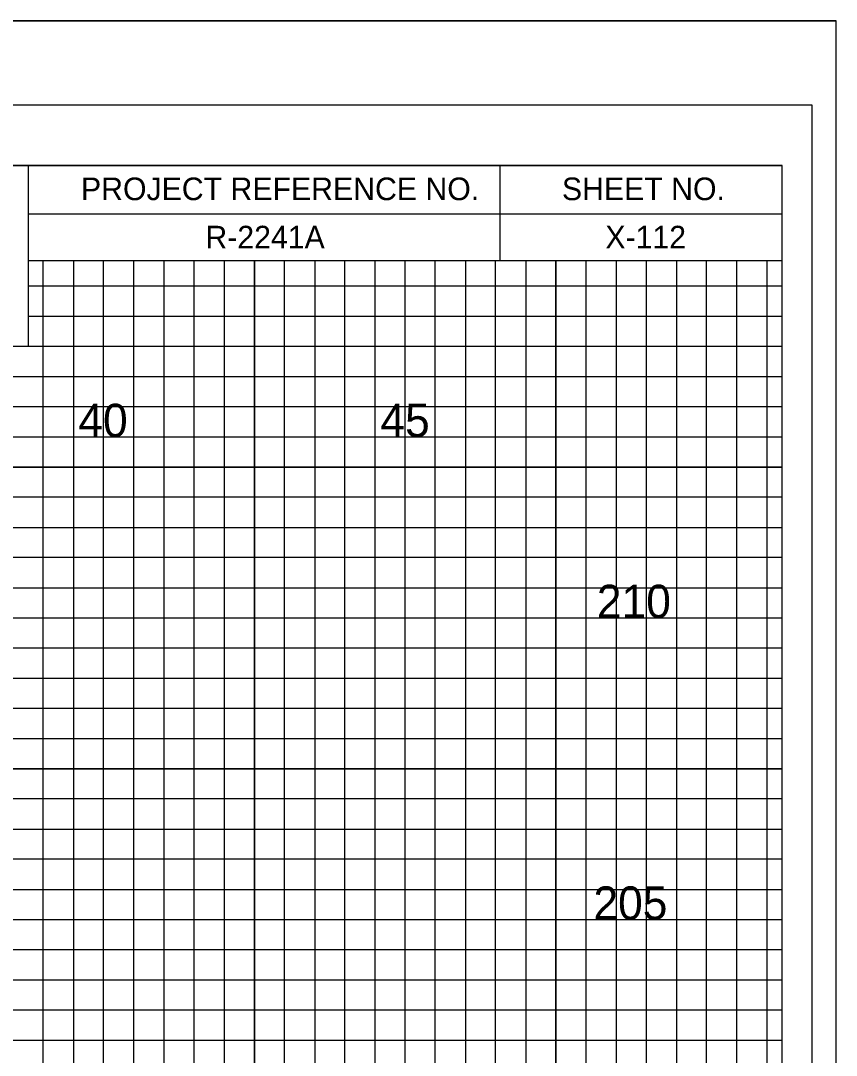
# Model space of a CAD drawing. Extents: x -4 to 103, y -2 to 492.
# Drawn here: x 89.88 to 103.4, y 121.08 to 138.23 of the extents above; entities that cross this region are included whole.
import ezdxf

# ---------------------------------------------------------------- set-up
doc = ezdxf.new("R2010")
doc.units = 0
for name, color, linetype in [('Exist XS Center Line Elevation Label', 7, 'Continuous'), ('Exist XS Ground Line', 7, 'Continuous'), ('Old_Level_10', 7, 'Continuous'), ('Old_Level_16', 7, 'Continuous'), ('Old_Level_3', 7, 'Continuous'), ('Old_Level_5', 7, 'Continuous'), ('Old_Level_8', 7, 'Continuous'), ('Prop Dimension', 7, 'Continuous'), ('Prop XS Finish Grade Earthwork', 7, 'Continuous'), ('Prop XS SE Text', 7, 'Continuous'), ('Prop XSC Text', 7, 'Continuous')]:
    doc.layers.add(name, color=color, linetype=linetype)

msp = doc.modelspace()

# ---------------------------------------------------------------- linework, layer by layer
at = {"layer": 'Old_Level_10'}
for p, q in [((91.25, 70.825), (91.25, 134.25)), ((93.75, 70.825), (93.75, 134.25)), ((96.25, 70.825), (96.25, 134.25)), ((98.75, 70.825), (98.75, 134.25)), ((101.25, 70.825), (101.25, 134.25)), ((90, 133.325), (102.5, 133.325)), ((0, 130.825), (102.5, 130.825)), ((0, 128.325), (102.5, 128.325)), ((0, 125.825), (102.5, 125.825)), ((0, 123.325), (102.5, 123.325))]:
    msp.add_line(p, q, dxfattribs=at)
at = {"layer": 'Old_Level_3'}
msp.add_line((-3.5, 138.225), (103.4, 138.225), dxfattribs=at)
at = {"layer": 'Old_Level_5'}
msp.add_lwpolyline([(103.4, 138.225), (-3.5, 138.225), (-3.5, 68.4), (103.4, 68.4)], close=True, dxfattribs=at)
at = {"layer": 'Old_Level_8'}
for points in [[(91.25, 70.825), (91.25, 134.25), (93.75, 134.25), (93.75, 70.825)], [(96.25, 70.825), (96.25, 134.25), (98.75, 134.25), (98.75, 70.825)], [(101.25, 70.825), (101.25, 134.25)], [(90, 133.325), (102.5, 133.325)], [(0, 128.325), (102.5, 128.325), (102.5, 130.825), (0, 130.825)], [(0, 123.325), (102.5, 123.325), (102.5, 125.825), (0, 125.825)]]:
    msp.add_lwpolyline(points, dxfattribs=at)
at = {"layer": 'Prop Dimension'}
for points in [[(90.25, 70.825), (90.25, 134.25), (90.75, 134.25), (90.75, 70.825)], [(91.75, 70.825), (91.75, 134.25), (92.25, 134.25), (92.25, 70.825)], [(92.75, 70.825), (92.75, 134.25), (93.25, 134.25), (93.25, 70.825)], [(94.25, 70.825), (94.25, 134.25), (94.75, 134.25), (94.75, 70.825)], [(95.25, 70.825), (95.25, 134.25), (95.75, 134.25), (95.75, 70.825)], [(96.75, 70.825), (96.75, 134.25), (97.25, 134.25), (97.25, 70.825)], [(97.75, 70.825), (97.75, 134.25), (98.25, 134.25), (98.25, 70.825)], [(99.25, 70.825), (99.25, 134.25), (99.75, 134.25), (99.75, 70.825)], [(100.25, 70.825), (100.25, 134.25)], [(100.25, 134.25), (100.75, 134.25), (100.75, 70.825), (101.75, 70.825), (101.75, 134.25), (102.25, 134.25), (102.25, 70.825)], [(102.5, 132.825), (102.5, 133.825), (90, 133.825)], [(0, 132.325), (102.5, 132.325), (102.5, 132.825), (0, 132.825)], [(0, 131.325), (102.5, 131.325), (102.5, 131.825), (0, 131.825)], [(0, 129.825), (102.5, 129.825), (102.5, 130.325), (0, 130.325)], [(0, 128.825), (102.5, 128.825), (102.5, 129.325), (0, 129.325)], [(0, 127.325), (102.5, 127.325), (102.5, 127.825), (0, 127.825)], [(0, 126.325), (102.5, 126.325), (102.5, 126.825), (0, 126.825)], [(0, 124.825), (102.5, 124.825), (102.5, 125.325), (0, 125.325)], [(0, 123.825), (102.5, 123.825), (102.5, 124.325), (0, 124.325)], [(0, 122.325), (102.5, 122.325), (102.5, 122.825), (0, 122.825)], [(0, 121.325), (102.5, 121.325), (102.5, 121.825), (0, 121.825)]]:
    msp.add_lwpolyline(points, dxfattribs=at)
at = {"layer": 'Prop XS SE Text'}
msp.add_lwpolyline([(103, 136.825), (-2.8, 136.825), (-2.8, 69.825), (103, 69.825)], close=True, dxfattribs=at)
at = {"layer": 'Prop XSC Text'}
for p, q in [((90, 135.825), (102.5, 135.825)), ((90, 135.825), (102.5, 135.825)), ((97.825, 134.25), (97.825, 135.825)), ((101.875, 135.825), (101.875, 135.825)), ((102.5, 135.825), (102.5, 135.825)), ((102.5, 134.25), (102.5, 135.825)), ((102.5, 135.825), (102.5, 135.825)), ((102.5, 135.825), (102.5, 135.825)), ((102.5, 134.25), (102.5, 135.825)), ((90, 135.025), (102.5, 135.025)), ((90, 134.25), (102.5, 134.25)), ((99.4, 134.25), (99.4, 134.25)), ((99.4, 134.25), (99.4, 134.25))]:
    msp.add_line(p, q, dxfattribs=at)
for points in [[(102.5, 135.825), (0, 135.825), (0, 70.825), (102.5, 70.825)], [(83.75, 135.825), (90, 135.825), (90, 132.825), (83.75, 132.825)]]:
    msp.add_lwpolyline(points, close=True, dxfattribs=at)

# ---------------------------------------------------------------- texts
at = {"layer": 'Exist XS Center Line Elevation Label'}
msp.add_text('R-2241A', height=0.375, dxfattribs=at).set_placement((92.9378, 134.45))
at = {"layer": 'Exist XS Ground Line'}
msp.add_text('X-112', height=0.375, dxfattribs=at).set_placement((99.5699, 134.45))
at = {"layer": 'Old_Level_16'}
for s, p in [('40', (90.8313, 131.325)), ('45', (95.8399, 131.325))]:
    msp.add_text(s, height=0.55, dxfattribs=at).set_placement(p)
at = {"layer": 'Prop XS Finish Grade Earthwork'}
for s, p in [('210', (99.4296, 128.325)), ('205', (99.3724, 123.325))]:
    msp.add_text(s, height=0.55, dxfattribs=at).set_placement(p)
at = {"layer": 'Prop XSC Text'}
for s, p in [('PROJECT REFERENCE NO.', (90.875, 135.25)), ('SHEET NO.', (98.85, 135.25))]:
    msp.add_text(s, height=0.375, dxfattribs=at).set_placement(p)

doc.saveas('drawing.dxf')
